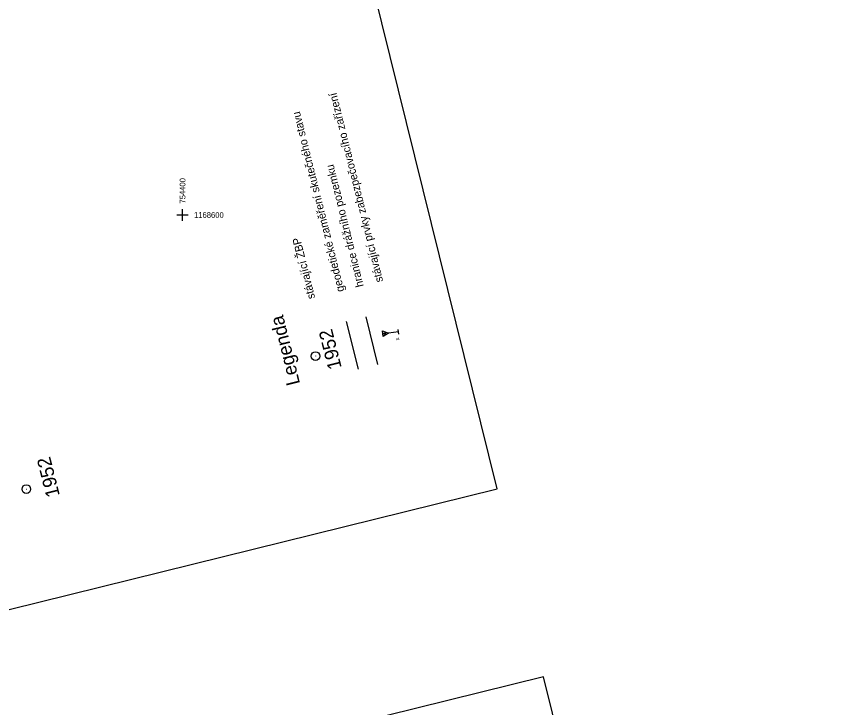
# Model space of a CAD drawing. Extents: x -754679 to -754173, y -1169241 to -1168288.
# Drawn here: x -754458.2 to -754172.8, y -1168772.6 to -1168530.4 of the extents above; entities that cross this region are included whole.
import ezdxf

# ---------------------------------------------------------------- set-up
doc = ezdxf.new("R2010")
doc.units = 0
for name, color, linetype in [('Default', 7, 'Continuous'), ('Vrstva 1', 7, 'Continuous'), ('Vrstva 2', 7, 'Continuous'), ('Vrstva 24', 7, 'Continuous'), ('Vrstva 27', 7, 'Continuous'), ('Vrstva 4', 7, 'Continuous'), ('Vrstva 61', 7, 'Continuous'), ('Vrstva 63', 7, 'Continuous')]:
    doc.layers.add(name, color=color, linetype=linetype)

msp = doc.modelspace()

# ---------------------------------------------------------------- linework, layer by layer
at = {"layer": 'Default'}
for points in [[(-754400, -1168602), (-754400, -1168600), (-754400, -1168598)], [(-754402, -1168600), (-754400, -1168600), (-754398, -1168600)]]:
    msp.add_lwpolyline(points, dxfattribs=at)
at = {"layer": 'Vrstva 1'}
msp.add_line((-754454.68, -1168695.98), (-754454.68, -1168695.98), dxfattribs=at)
at = {"layer": 'Vrstva 24'}
msp.add_line((-754331.66, -1168652.34), (-754335.79, -1168635.66), dxfattribs=at)
at = {"layer": 'Vrstva 27'}
msp.add_line((-754338.45, -1168654.02), (-754342.58, -1168637.34), dxfattribs=at)
at = {"layer": 'Vrstva 4'}
for p, q in [((-754329.03, -1168641.72), (-754329.42, -1168641.42)), ((-754324.33, -1168641.7), (-754324.52, -1168640.16))]:
    msp.add_line(p, q, dxfattribs=at)
msp.add_lwpolyline([(-754324.43, -1168640.93), (-754327.88, -1168641.37), (-754329.74, -1168642.6), (-754330, -1168640.62), (-754327.88, -1168641.37)], dxfattribs=at)
msp.add_circle((-754329.23, -1168641.57), 0.248, dxfattribs=at)
at = {"layer": 'Vrstva 61'}
for points in [[(-754578.24, -1168767.26), (-754289.93, -1168695.96), (-754390.75, -1168288.24), (-754679.07, -1168359.54)], [(-754461.15, -1169240.8), (-754172.83, -1169169.5), (-754273.65, -1168761.78), (-754561.97, -1168833.08)]]:
    msp.add_lwpolyline(points, dxfattribs=at)
at = {"layer": 'Vrstva 63'}
for p, q in [((-754353.48, -1168649.3), (-754353.47, -1168649.5)), ((-754454.78, -1168695.98), (-754454.58, -1168695.98))]:
    msp.add_line(p, q, dxfattribs=at)
for centre in [(-754353.48, -1168649.4), (-754454.68, -1168695.98)]:
    msp.add_circle(centre, 1.51, dxfattribs=at)

# ---------------------------------------------------------------- texts
at = {"layer": 'Default'}
msp.add_text('754400', height=2, rotation=90, dxfattribs=at).set_placement((-754399, -1168596))
msp.add_text('1168600', height=2, dxfattribs=at).set_placement((-754396, -1168601))
at = {"layer": 'Vrstva 2'}
for p in [(-754344.26, -1168653.45), (-754442.91, -1168698.2)]:
    msp.add_text('1952', height=4.8, rotation=104.1384, dxfattribs=at).set_placement(p)
at = {"layer": 'Vrstva 27'}
for s, height, p in [('stávající prvky zabezpečovacího zařízení', 2.8, (-754329.79, -1168623.21)), ('geodetické zaměření skutečného stavu', 2.8, (-754343.38, -1168626.57)), ('hranice drážního pozemku', 2.8, (-754336.58, -1168624.89)), ('stávající ŽBP', 2.8, (-754353.57, -1168629.09)), ('Legenda', 4.8, (-754358.84, -1168659.06))]:
    msp.add_text(s, height=height, rotation=103.9106, dxfattribs=at).set_placement(p)
at = {"layer": 'Vrstva 4'}
msp.add_text('B', height=1, rotation=100, dxfattribs=at).set_placement((-754324.14, -1168643.8))

doc.saveas('drawing.dxf')
